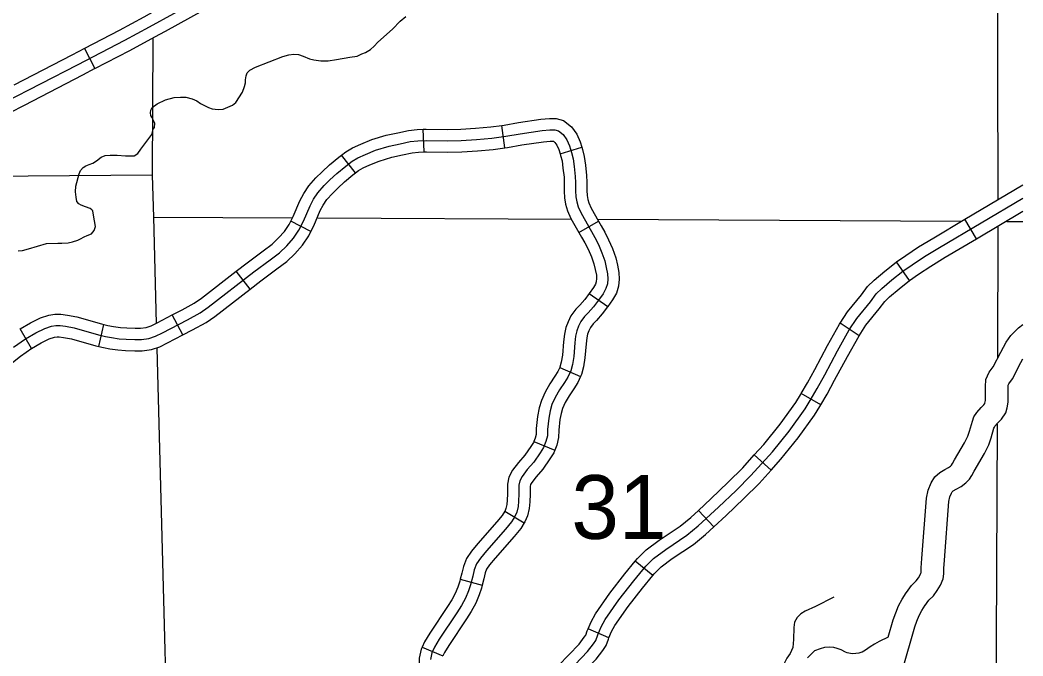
# Model space of a CAD drawing. Extents: x -3711 to 825, y -151 to 1050.
# Drawn here: x -2609.5 to -2535.1, y 288.6 to 335.8 of the extents above; entities that cross this region are included whole.
import ezdxf

# ---------------------------------------------------------------- set-up
doc = ezdxf.new("R2010")
doc.units = 0
for name, color, linetype in [('Level 31', 7, 'Continuous'), ('Level 32', 7, 'Continuous'), ('Level 35', 7, 'Continuous'), ('Level 4', 7, 'Continuous'), ('Level 46', 7, 'Continuous'), ('Level 5', 7, 'Continuous')]:
    doc.layers.add(name, color=color, linetype=linetype)

msp = doc.modelspace()

# ---------------------------------------------------------------- linework, layer by layer
at = {"layer": 'Level 31'}
msp.add_line((-2604.774, 333.647), (-2603.992, 332.158), dxfattribs=at)
for points in [[(-2598.756, 334.951), (-2595.95, 336.494), (-2594.883, 337.122), (-2593.591, 337.939)], [(-2596.366, 337.225), (-2599.959, 335.248), (-2601.803, 334.257), (-2605.316, 332.412), (-2610.692, 329.635)], [(-2599.567, 336.424), (-2600.361, 335.986), (-2602.198, 335), (-2604.774, 333.647)], [(-2603.992, 332.158), (-2601.409, 333.515), (-2599.558, 334.509), (-2598.756, 334.951)], [(-2604.774, 333.647), (-2605.704, 333.158), (-2610.023, 330.927)], [(-2603.992, 332.158), (-2604.928, 331.667), (-2609.251, 329.433)], [(-2609.251, 329.433), (-2610.309, 328.887), (-2610.799, 328.638), (-2611.282, 328.356), (-2611.785, 328.037), (-2612.466, 327.579), (-2613.191, 327.088), (-2614.184, 326.391)]]:
    msp.add_lwpolyline(points, dxfattribs=at)
at = {"layer": 'Level 32'}
for p, q in [((-2579.579, 325.972), (-2579.633, 327.652)), ((-2573.589, 326.282), (-2573.818, 327.947)), ((-2569.484, 325.821), (-2567.883, 326.333)), ((-2584.666, 324.411), (-2585.702, 325.735)), ((-2587.965, 320.066), (-2589.46, 320.836)), ((-2568.093, 319.995), (-2566.63, 320.824)), ((-2538.592, 319.526), (-2539.449, 320.972)), ((-2543.555, 316.436), (-2544.527, 317.807)), ((-2592.479, 315.786), (-2593.508, 317.115)), ((-2567.323, 315.46), (-2565.951, 314.489)), ((-2597.482, 312.387), (-2598.26, 313.877)), ((-2547.307, 312.328), (-2548.713, 313.248)), ((-2608.707, 311.385), (-2609.549, 312.839)), ((-2603.716, 311.522), (-2603.338, 313.16)), ((-2569.505, 309.976), (-2567.963, 309.306)), ((-2550.143, 307.186), (-2551.597, 308.029)), ((-2571.435, 304.472), (-2569.879, 303.836)), ((-2553.833, 302.35), (-2555.082, 303.476)), ((-2573.582, 299.309), (-2572.14, 298.444)), ((-2558.085, 298.129), (-2559.226, 299.364)), ((-2562.605, 294.524), (-2563.908, 295.587)), ((-2576.887, 294.252), (-2575.269, 293.797)), ((-2565.866, 289.895), (-2567.412, 290.556)), ((-2579.719, 289.214), (-2578.174, 288.552))]:
    msp.add_line(p, q, dxfattribs=at)
for points in [[(-2573.818, 327.947), (-2573.639, 327.972), (-2572.576, 328.152), (-2570.904, 328.4), (-2570.278, 328.445), (-2569.77, 328.445), (-2569.222, 328.318), (-2568.646, 327.844), (-2568.241, 327.293), (-2568.007, 326.723), (-2567.883, 326.333)], [(-2610.028, 311.479), (-2609.142, 312.104), (-2608.377, 312.547), (-2607.712, 312.87), (-2607.208, 313.031), (-2606.886, 313.091), (-2606.584, 313.091), (-2606.181, 313.031), (-2605.537, 312.91), (-2603.724, 312.386), (-2603.2, 312.265), (-2602.757, 312.184), (-2602.193, 312.104), (-2601.669, 312.064), (-2601.025, 312.043), (-2600.542, 312.043), (-2599.998, 312.124), (-2599.494, 312.285), (-2598.991, 312.547), (-2597.138, 313.515), (-2596.191, 314.019), (-2595.587, 314.442), (-2592.203, 317.062), (-2590.994, 317.969), (-2590.309, 318.493), (-2589.766, 318.997), (-2589.262, 319.562), (-2588.859, 320.167), (-2588.517, 320.832), (-2588.033, 321.981), (-2587.772, 322.464), (-2587.449, 322.948), (-2586.986, 323.472), (-2586.563, 323.895), (-2586.039, 324.379), (-2585.375, 324.923), (-2584.911, 325.286), (-2584.911, 325.286), (-2584.488, 325.528), (-2583.924, 325.79), (-2583.179, 326.093), (-2582.172, 326.395), (-2581.346, 326.576), (-2580.601, 326.738), (-2580.037, 326.798), (-2579.413, 326.818), (-2577.862, 326.798), (-2576.814, 326.818), (-2575.686, 326.899), (-2574.538, 327), (-2573.511, 327.141), (-2572.444, 327.322), (-2570.812, 327.564), (-2570.248, 327.604), (-2569.865, 327.604), (-2569.604, 327.544), (-2569.261, 327.262), (-2568.979, 326.879), (-2568.798, 326.435), (-2568.637, 325.931), (-2568.516, 325.468), (-2568.435, 324.883), (-2568.355, 324.158), (-2568.335, 323.714), (-2568.335, 323.089), (-2568.315, 322.646), (-2568.254, 322.263), (-2568.153, 321.9), (-2567.932, 321.416), (-2567.166, 320.066), (-2566.905, 319.622), (-2566.643, 319.098), (-2566.381, 318.493), (-2566.159, 317.889), (-2566.059, 317.405), (-2565.958, 316.921), (-2565.938, 316.558), (-2565.978, 316.175), (-2566.079, 315.833), (-2566.3, 315.45), (-2566.643, 314.966), (-2567.005, 314.482), (-2567.408, 314.039), (-2567.67, 313.757), (-2567.952, 313.374), (-2568.113, 313.031), (-2568.254, 312.688), (-2568.335, 312.305), (-2568.395, 311.801), (-2568.476, 310.794), (-2568.576, 310.189), (-2568.697, 309.725)], [(-2585.702, 325.735), (-2585.382, 325.986), (-2584.875, 326.276), (-2584.26, 326.561), (-2583.459, 326.886), (-2582.383, 327.209), (-2581.525, 327.398), (-2580.735, 327.569), (-2580.096, 327.637), (-2579.633, 327.652)], [(-2579.633, 327.652), (-2579.421, 327.659), (-2577.864, 327.639), (-2576.852, 327.658), (-2575.753, 327.737), (-2574.632, 327.835), (-2573.818, 327.947)], [(-2573.589, 326.282), (-2573.384, 326.31), (-2572.312, 326.492), (-2570.72, 326.728), (-2570.218, 326.764), (-2569.979, 326.764), (-2569.876, 326.679), (-2569.718, 326.464), (-2569.589, 326.148), (-2569.484, 325.821)], [(-2584.666, 324.411), (-2584.441, 324.587), (-2584.102, 324.781), (-2583.589, 325.019), (-2582.9, 325.299), (-2581.961, 325.581), (-2581.167, 325.755), (-2580.467, 325.907), (-2579.979, 325.959), (-2579.579, 325.972)], [(-2579.579, 325.972), (-2579.405, 325.977), (-2577.859, 325.957), (-2576.776, 325.978), (-2575.62, 326.061), (-2574.444, 326.164), (-2573.589, 326.282)], [(-2567.883, 326.333), (-2567.829, 326.166), (-2567.69, 325.632), (-2567.601, 324.987), (-2567.516, 324.223), (-2567.494, 323.733), (-2567.494, 323.108), (-2567.477, 322.731), (-2567.431, 322.441), (-2567.361, 322.189), (-2567.183, 321.799), (-2566.63, 320.824)], [(-2589.46, 320.836), (-2589.279, 321.188), (-2588.792, 322.345), (-2588.493, 322.898), (-2588.117, 323.462), (-2587.599, 324.048), (-2587.146, 324.502), (-2586.591, 325.014), (-2585.9, 325.58), (-2585.702, 325.735)], [(-2569.484, 325.821), (-2569.444, 325.697), (-2569.342, 325.304), (-2569.27, 324.779), (-2569.193, 324.092), (-2569.175, 323.695), (-2569.175, 323.07), (-2569.152, 322.561), (-2569.077, 322.084), (-2568.946, 321.611), (-2568.681, 321.033), (-2568.093, 319.995)], [(-2587.965, 320.066), (-2587.755, 320.476), (-2587.275, 321.617), (-2587.051, 322.03), (-2586.782, 322.434), (-2586.373, 322.896), (-2585.98, 323.289), (-2585.487, 323.745), (-2584.849, 324.267), (-2584.666, 324.411)], [(-2539.449, 320.972), (-2535.146, 323.522)], [(-2569.727, 286.493), (-2567.439, 288.871), (-2567.004, 289.451), (-2566.83, 289.711), (-2566.685, 290.117), (-2566.425, 290.726), (-2566.135, 291.248), (-2565.121, 292.727), (-2564.02, 294.118), (-2563.122, 295.22), (-2562.543, 295.8), (-2561.645, 296.467), (-2560.08, 297.51), (-2559.24, 298.206), (-2557.733, 299.598), (-2556.43, 300.844), (-2555.329, 301.946), (-2553.736, 303.715), (-2552.49, 305.251), (-2551.302, 306.904), (-2550.925, 307.512), (-2550.404, 308.411), (-2549.854, 309.426), (-2548.898, 311.194), (-2548.028, 312.76), (-2547.478, 313.601), (-2546.464, 314.847), (-2546.029, 315.427), (-2545.624, 315.833), (-2544.871, 316.471), (-2544.059, 317.109), (-2543.364, 317.602), (-2542.437, 318.21), (-2541.336, 318.877), (-2535.146, 322.545)], [(-2538.592, 319.526), (-2535.146, 321.568)], [(-2593.508, 317.115), (-2592.712, 317.731), (-2591.502, 318.639), (-2590.852, 319.137), (-2590.366, 319.587), (-2589.929, 320.077), (-2589.585, 320.593), (-2589.46, 320.836)], [(-2566.63, 320.824), (-2566.439, 320.487), (-2566.166, 320.024), (-2565.881, 319.453), (-2565.6, 318.805), (-2565.349, 318.12), (-2565.236, 317.576), (-2565.122, 317.031), (-2565.095, 316.538), (-2565.15, 316.012), (-2565.301, 315.499), (-2565.592, 314.996), (-2565.951, 314.489)], [(-2544.527, 317.807), (-2543.838, 318.296), (-2542.886, 318.921), (-2541.768, 319.598), (-2539.449, 320.972)], [(-2592.479, 315.786), (-2591.693, 316.394), (-2590.487, 317.299), (-2589.767, 317.85), (-2589.165, 318.408), (-2588.595, 319.046), (-2588.133, 319.74), (-2587.965, 320.066)], [(-2568.093, 319.995), (-2567.894, 319.645), (-2567.643, 319.22), (-2567.405, 318.743), (-2567.162, 318.182), (-2566.97, 317.657), (-2566.882, 317.234), (-2566.794, 316.812), (-2566.781, 316.579), (-2566.806, 316.339), (-2566.857, 316.167), (-2567.009, 315.904), (-2567.323, 315.46)], [(-2543.555, 316.436), (-2542.89, 316.907), (-2541.988, 317.499), (-2540.904, 318.156), (-2538.592, 319.526)], [(-2548.713, 313.248), (-2548.157, 314.097), (-2547.127, 315.365), (-2546.666, 315.979), (-2546.194, 316.452), (-2545.402, 317.122), (-2544.563, 317.782), (-2544.527, 317.807)], [(-2598.26, 313.877), (-2597.53, 314.258), (-2596.631, 314.737), (-2596.085, 315.119), (-2593.508, 317.115)], [(-2547.307, 312.328), (-2546.798, 313.104), (-2545.801, 314.33), (-2545.393, 314.875), (-2545.054, 315.214), (-2544.339, 315.82), (-2543.556, 316.435), (-2543.555, 316.436)], [(-2597.482, 312.387), (-2596.746, 312.771), (-2595.751, 313.301), (-2595.088, 313.765), (-2592.479, 315.786)], [(-2567.322, 315.461), (-2567.654, 315.018), (-2568.027, 314.607), (-2568.319, 314.293), (-2568.678, 313.806), (-2568.883, 313.37), (-2569.061, 312.937), (-2569.165, 312.442), (-2569.232, 311.885), (-2569.311, 310.896), (-2569.399, 310.364), (-2569.494, 310.001), (-2569.505, 309.976)], [(-2565.951, 314.489), (-2565.963, 314.471), (-2566.356, 313.946), (-2566.789, 313.47), (-2567.021, 313.22), (-2567.226, 312.942), (-2567.344, 312.692), (-2567.447, 312.44), (-2567.504, 312.169), (-2567.559, 311.718), (-2567.641, 310.691), (-2567.753, 310.014), (-2567.9, 309.45), (-2567.963, 309.306)], [(-2609.549, 312.839), (-2608.771, 313.29), (-2608.025, 313.652), (-2607.415, 313.848), (-2606.964, 313.932), (-2606.521, 313.932), (-2606.041, 313.86), (-2605.342, 313.729), (-2603.512, 313.2), (-2603.338, 313.16)], [(-2603.338, 313.16), (-2603.03, 313.089), (-2602.622, 313.014), (-2602.101, 312.94), (-2601.624, 312.903), (-2601.012, 312.884), (-2600.604, 312.884), (-2600.189, 312.945), (-2599.819, 313.064), (-2599.379, 313.293), (-2598.26, 313.877)], [(-2551.597, 308.029), (-2551.137, 308.823), (-2550.593, 309.826), (-2549.635, 311.598), (-2548.749, 313.195), (-2548.713, 313.248)], [(-2608.707, 311.385), (-2607.982, 311.804), (-2607.399, 312.087), (-2607.002, 312.214), (-2606.808, 312.251), (-2606.647, 312.251), (-2606.321, 312.202), (-2605.731, 312.091), (-2603.935, 311.572), (-2603.716, 311.522)], [(-2603.716, 311.522), (-2603.37, 311.442), (-2602.892, 311.355), (-2602.285, 311.268), (-2601.715, 311.224), (-2601.038, 311.203), (-2600.48, 311.203), (-2599.807, 311.303), (-2599.17, 311.507), (-2598.602, 311.802), (-2597.482, 312.387)], [(-2550.143, 307.186), (-2549.671, 308), (-2549.114, 309.026), (-2548.16, 310.79), (-2547.308, 312.325), (-2547.307, 312.328)], [(-2613.618, 307.967), (-2613.122, 308.194), (-2612.095, 308.806), (-2611.125, 309.545), (-2609.526, 310.805), (-2608.688, 311.395), (-2608.706, 311.385)], [(-2568.697, 309.725), (-2568.899, 309.262), (-2569.161, 308.859), (-2569.523, 308.314), (-2569.845, 307.75), (-2570.087, 307.226), (-2570.228, 306.762), (-2570.329, 306.218), (-2570.409, 305.371), (-2570.429, 304.888), (-2570.53, 304.464), (-2570.711, 304.021), (-2570.953, 303.638), (-2571.437, 302.933), (-2571.92, 302.388), (-2572.303, 301.884), (-2572.479, 301.553), (-2572.536, 301.228), (-2572.548, 300.858), (-2572.536, 300.579), (-2572.564, 300.05), (-2572.605, 299.647), (-2572.705, 299.224), (-2572.846, 298.901), (-2573.088, 298.498), (-2573.531, 297.974), (-2574.941, 296.361), (-2575.384, 295.817), (-2575.686, 295.394), (-2575.848, 294.95), (-2575.948, 294.487), (-2576.13, 293.842), (-2576.291, 293.378), (-2576.492, 292.834), (-2576.794, 292.29), (-2577.137, 291.766), (-2578.446, 289.79), (-2578.808, 289.206), (-2578.99, 288.783), (-2579.111, 288.279)], [(-2569.505, 309.976), (-2569.642, 309.661), (-2569.863, 309.321), (-2570.239, 308.756), (-2570.593, 308.135), (-2570.875, 307.526), (-2571.046, 306.962), (-2571.162, 306.335), (-2571.248, 305.429), (-2571.266, 305.004), (-2571.333, 304.722), (-2571.435, 304.472)], [(-2567.963, 309.306), (-2568.156, 308.863), (-2568.458, 308.397), (-2568.807, 307.872), (-2569.097, 307.365), (-2569.3, 306.926), (-2569.41, 306.563), (-2569.495, 306.102), (-2569.57, 305.314), (-2569.593, 304.772), (-2569.727, 304.207), (-2569.879, 303.836)], [(-2555.082, 303.476), (-2554.375, 304.261), (-2553.158, 305.762), (-2552.002, 307.371), (-2551.647, 307.945), (-2551.597, 308.029)], [(-2553.833, 302.35), (-2553.096, 303.168), (-2551.822, 304.741), (-2550.602, 306.437), (-2550.204, 307.08), (-2550.143, 307.186)], [(-2571.435, 304.472), (-2571.462, 304.407), (-2571.656, 304.1), (-2572.1, 303.451), (-2572.57, 302.922), (-2573.013, 302.339), (-2573.283, 301.83), (-2573.375, 301.316), (-2573.389, 300.853), (-2573.378, 300.584), (-2573.403, 300.114), (-2573.436, 299.787), (-2573.506, 299.491), (-2573.595, 299.287), (-2573.582, 299.309)], [(-2569.879, 303.836), (-2569.961, 303.635), (-2570.251, 303.176), (-2570.773, 302.414), (-2571.27, 301.854), (-2571.592, 301.43), (-2571.674, 301.275), (-2571.698, 301.141), (-2571.707, 300.862), (-2571.695, 300.575), (-2571.726, 299.986), (-2571.774, 299.507), (-2571.905, 298.956), (-2572.098, 298.515), (-2572.14, 298.444)], [(-2559.226, 299.364), (-2558.309, 300.21), (-2557.018, 301.445), (-2555.939, 302.525), (-2555.082, 303.476)], [(-2558.085, 298.129), (-2557.158, 298.985), (-2555.842, 300.243), (-2554.719, 301.367), (-2553.833, 302.35)], [(-2573.582, 299.309), (-2573.774, 298.989), (-2574.169, 298.522), (-2575.584, 296.904), (-2576.053, 296.327), (-2576.437, 295.789), (-2576.657, 295.184), (-2576.764, 294.69), (-2576.887, 294.252)], [(-2563.908, 295.587), (-2563.747, 295.784), (-2563.093, 296.438), (-2562.129, 297.154), (-2560.583, 298.185), (-2559.794, 298.839), (-2559.226, 299.364)], [(-2572.14, 298.444), (-2572.402, 298.007), (-2572.894, 297.426), (-2574.299, 295.819), (-2574.716, 295.307), (-2574.936, 294.999), (-2575.038, 294.717), (-2575.132, 294.284), (-2575.269, 293.797)], [(-2562.605, 294.524), (-2562.497, 294.656), (-2561.992, 295.162), (-2561.16, 295.779), (-2559.577, 296.835), (-2558.686, 297.573), (-2558.085, 298.129)], [(-2567.412, 290.556), (-2567.18, 291.097), (-2566.851, 291.691), (-2565.798, 293.226), (-2564.676, 294.645), (-2563.908, 295.587)], [(-2576.887, 294.252), (-2576.932, 294.094), (-2577.082, 293.662), (-2577.258, 293.186), (-2577.515, 292.724), (-2577.839, 292.228), (-2579.154, 290.244), (-2579.556, 289.595), (-2579.719, 289.214)], [(-2565.866, 289.895), (-2565.669, 290.356), (-2565.419, 290.805), (-2564.444, 292.228), (-2563.365, 293.592), (-2562.605, 294.524)], [(-2575.269, 293.797), (-2575.327, 293.59), (-2575.499, 293.094), (-2575.726, 292.482), (-2576.074, 291.855), (-2576.434, 291.304), (-2577.738, 289.337), (-2578.061, 288.817), (-2578.174, 288.552)], [(-2571.03, 286.224), (-2570.357, 287.051), (-2568.08, 289.416), (-2567.691, 289.936), (-2567.587, 290.091), (-2567.468, 290.424), (-2567.412, 290.556)], [(-2569.726, 285.163), (-2569.097, 285.936), (-2566.797, 288.325), (-2566.317, 288.965), (-2566.073, 289.332), (-2565.902, 289.81), (-2565.866, 289.895)], [(-2579.719, 289.214), (-2579.791, 289.048), (-2579.951, 288.378), (-2579.951, 287.864), (-2579.931, 287.138), (-2579.931, 286.602), (-2579.962, 286.25), (-2580.054, 285.91), (-2580.239, 285.391), (-2580.792, 284.008), (-2581.001, 283.532)]]:
    msp.add_lwpolyline(points, dxfattribs=at)
at = {"layer": 'Level 35'}
for points in [[(-2585.095, 332.998), (-2584.551, 333.095), (-2584.182, 333.251), (-2583.93, 333.348), (-2583.542, 333.581), (-2583.27, 333.814), (-2582.998, 334.125), (-2581.93, 335.097), (-2581.347, 335.68), (-2580.94, 336.029)], [(-2609.696, 318.619), (-2609.366, 318.658), (-2608.919, 318.775), (-2607.579, 319.163), (-2606.744, 319.202), (-2606.453, 319.202), (-2605.987, 319.222), (-2605.657, 319.299), (-2605.269, 319.416), (-2605.075, 319.513), (-2604.783, 319.669), (-2604.57, 319.766), (-2604.259, 319.882), (-2604.045, 320.135), (-2603.948, 320.426), (-2604.104, 321.281), (-2604.162, 321.592), (-2604.22, 321.67), (-2604.356, 321.767), (-2604.686, 321.903), (-2605.016, 322.02), (-2605.191, 322.117), (-2605.327, 322.292), (-2605.385, 322.622), (-2605.424, 323.011), (-2605.405, 323.438), (-2605.172, 324.351), (-2605.055, 324.585), (-2604.861, 324.818), (-2604.667, 324.934), (-2604.414, 325.051), (-2604.162, 325.148), (-2603.871, 325.323), (-2603.521, 325.595), (-2603.23, 325.712), (-2602.861, 325.731), (-2602.356, 325.731), (-2601.715, 325.692), (-2601.385, 325.673), (-2601.094, 325.692), (-2600.822, 325.867), (-2600.589, 326.178), (-2599.774, 327.266), (-2599.677, 327.655), (-2599.58, 327.791), (-2599.56, 328.082), (-2599.677, 328.354), (-2599.774, 328.549), (-2599.851, 328.685), (-2599.871, 328.879), (-2599.851, 329.073), (-2599.754, 329.267), (-2599.366, 329.539), (-2598.764, 329.831), (-2598.104, 330.006), (-2597.657, 330.045), (-2597.25, 330.045), (-2596.784, 329.928), (-2596.434, 329.773), (-2596.162, 329.578), (-2595.871, 329.423), (-2595.58, 329.267), (-2595.308, 329.17), (-2594.842, 329.131), (-2594.473, 329.151), (-2594.143, 329.287), (-2593.793, 329.442), (-2593.541, 329.637), (-2593.036, 330.414), (-2592.91, 330.832), (-2592.835, 331.094), (-2592.816, 331.319), (-2592.764, 331.619), (-2592.706, 331.852), (-2592.512, 332.046), (-2592.085, 332.26), (-2590.066, 333.056), (-2589.619, 333.173), (-2589.231, 333.231), (-2588.901, 333.212), (-2588.551, 333.095), (-2588.066, 332.882), (-2587.755, 332.804), (-2587.231, 332.746), (-2586.687, 332.746), (-2586.066, 332.843), (-2585.095, 332.998)], [(-2549.165, 292.928), (-2550.548, 292.216), (-2551.3, 291.89), (-2551.626, 291.687), (-2551.89, 291.402), (-2552.093, 291.056), (-2552.134, 290.67), (-2552.174, 289.774), (-2552.215, 289.184), (-2552.418, 288.737), (-2552.662, 288.391), (-2552.947, 287.801), (-2553.293, 287.435), (-2553.679, 286.763), (-2554.004, 286.112), (-2554.106, 285.766), (-2554.228, 285.42), (-2554.309, 284.973), (-2554.3, 284.693), (-2554.226, 284.277), (-2554.136, 283.935), (-2554.071, 283.033)]]:
    msp.add_lwpolyline(points, dxfattribs=at)
at = {"layer": 'Level 4'}
for points in [[(-2599.699, 334.418), (-2599.744, 324.254)], [(-2599.744, 324.254), (-2599.661, 321.138), (-2599.451, 313.242)], [(-2599.402, 311.412), (-2598.182, 265.63)]]:
    msp.add_lwpolyline(points, dxfattribs=at)
at = {"layer": 'Level 46'}
msp.add_line((-2543.818, 293.227), (-2543.789, 293.269), dxfattribs=at)
for points in [[(-2543.789, 293.269), (-2543.409, 293.786), (-2543.064, 294.131), (-2542.903, 294.346), (-2542.762, 294.576), (-2542.711, 294.698), (-2542.705, 294.752), (-2542.705, 295.104), (-2542.654, 295.798), (-2542.307, 300.262), (-2542.182, 300.856), (-2541.953, 301.413), (-2541.679, 301.844), (-2541.308, 302.173), (-2540.93, 302.394), (-2540.666, 302.536), (-2540.517, 302.655), (-2540.447, 302.726), (-2540.382, 302.83), (-2540.217, 303.113), (-2539.475, 304.382), (-2539.244, 304.866), (-2539.117, 305.245), (-2538.893, 305.995), (-2538.78, 306.296), (-2538.572, 306.629), (-2538.238, 306.993), (-2538.039, 307.192), (-2537.97, 307.296), (-2537.966, 307.313), (-2537.933, 307.529), (-2537.933, 308.522), (-2537.896, 309.072), (-2537.647, 309.612), (-2537.343, 310.018), (-2536.785, 311.112), (-2536.392, 311.846), (-2536.053, 312.34), (-2535.754, 312.639), (-2535.467, 312.926), (-2535.146, 313.167)], [(-2542.436, 292.273), (-2542.13, 292.687), (-2541.79, 293.027), (-2541.511, 293.4), (-2541.261, 293.807), (-2541.067, 294.273), (-2541.024, 294.659), (-2541.024, 295.042), (-2540.977, 295.671), (-2540.639, 300.023), (-2540.568, 300.359), (-2540.454, 300.636), (-2540.386, 300.744), (-2540.316, 300.806), (-2540.107, 300.928), (-2539.734, 301.129), (-2539.394, 301.401), (-2539.122, 301.673), (-2538.942, 301.961), (-2538.765, 302.266), (-2537.989, 303.594), (-2537.682, 304.236), (-2537.514, 304.738), (-2537.299, 305.458), (-2537.265, 305.548), (-2537.228, 305.607), (-2537.023, 305.831), (-2536.733, 306.122), (-2536.41, 306.606), (-2536.316, 306.981), (-2536.252, 307.401), (-2536.252, 308.466), (-2536.239, 308.65), (-2536.195, 308.747), (-2535.911, 309.125), (-2535.295, 310.333), (-2535.146, 310.612)], [(-2545.14, 289.942), (-2544.769, 291.244), (-2544.58, 291.757), (-2544.366, 292.265), (-2544.113, 292.772), (-2543.818, 293.227)], [(-2544.086, 287.511), (-2543.169, 290.722), (-2543.015, 291.14), (-2542.838, 291.563), (-2542.65, 291.937), (-2542.407, 292.315)], [(-2545.14, 289.942), (-2545.808, 289.629), (-2546.161, 289.431), (-2546.492, 289.232), (-2546.833, 288.992), (-2547.069, 288.844), (-2547.175, 288.799), (-2547.323, 288.765), (-2547.551, 288.735), (-2547.763, 288.721), (-2547.937, 288.732), (-2548.186, 288.788), (-2548.315, 288.831), (-2548.639, 289.002), (-2548.938, 289.111), (-2549.166, 289.176), (-2549.478, 289.215), (-2549.859, 289.181), (-2550.18, 289.093), (-2550.604, 288.939), (-2550.873, 288.669), (-2551.133, 288.41)]]:
    msp.add_lwpolyline(points, dxfattribs=at)
at = {"layer": 'Level 5'}
for points in [[(-2536.984, 322.452), (-2537.044, 342.413)], [(-2599.744, 324.254), (-2618.163, 324.094)], [(-2599.661, 321.138), (-2589.352, 321.086)], [(-2587.469, 321.077), (-2568.646, 320.981)], [(-2566.68, 320.971), (-2539.723, 320.835)], [(-2536.35, 320.815), (-2535.146, 320.805)], [(-2537.02, 310.722), (-2536.981, 320.439)], [(-2537.171, 273.473), (-2537.04, 305.771)]]:
    msp.add_lwpolyline(points, dxfattribs=at)

# ---------------------------------------------------------------- texts
msp.add_text('31', height=4.7343, dxfattribs=at).set_placement((-2568.644, 297.244))

doc.saveas('drawing.dxf')
